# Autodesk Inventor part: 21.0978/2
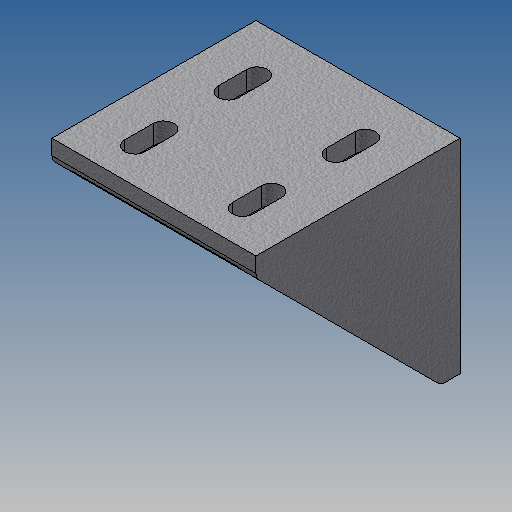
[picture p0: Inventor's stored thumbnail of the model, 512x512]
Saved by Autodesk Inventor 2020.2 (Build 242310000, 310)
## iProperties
Created: 2012-01
Part Number: 21.0978/2
Document SubType Name: Modeling
Designer: Administrator
Density: 2.7 g/cm^3
Material: Aluminum-6061
Mass: 359.078 g
Surface Area: 434.602 cm^2
Volume: 132.992 cm^3
Appearance: Aluminum Cast
Description: ANGLE 90 AL CASTING
Translation Standard: STEP AP214IS
FileName: 21_0978_0_2.stp
PreProcessor: ACIS
PostProcessor: Build: 236a, Release: 2009 RTM - Date: Fri 02/22/2008
Sent Units: CM
Uncertainty: 0.0
Author: Administrator
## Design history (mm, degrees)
feature "Base1"
body "Solid1"
